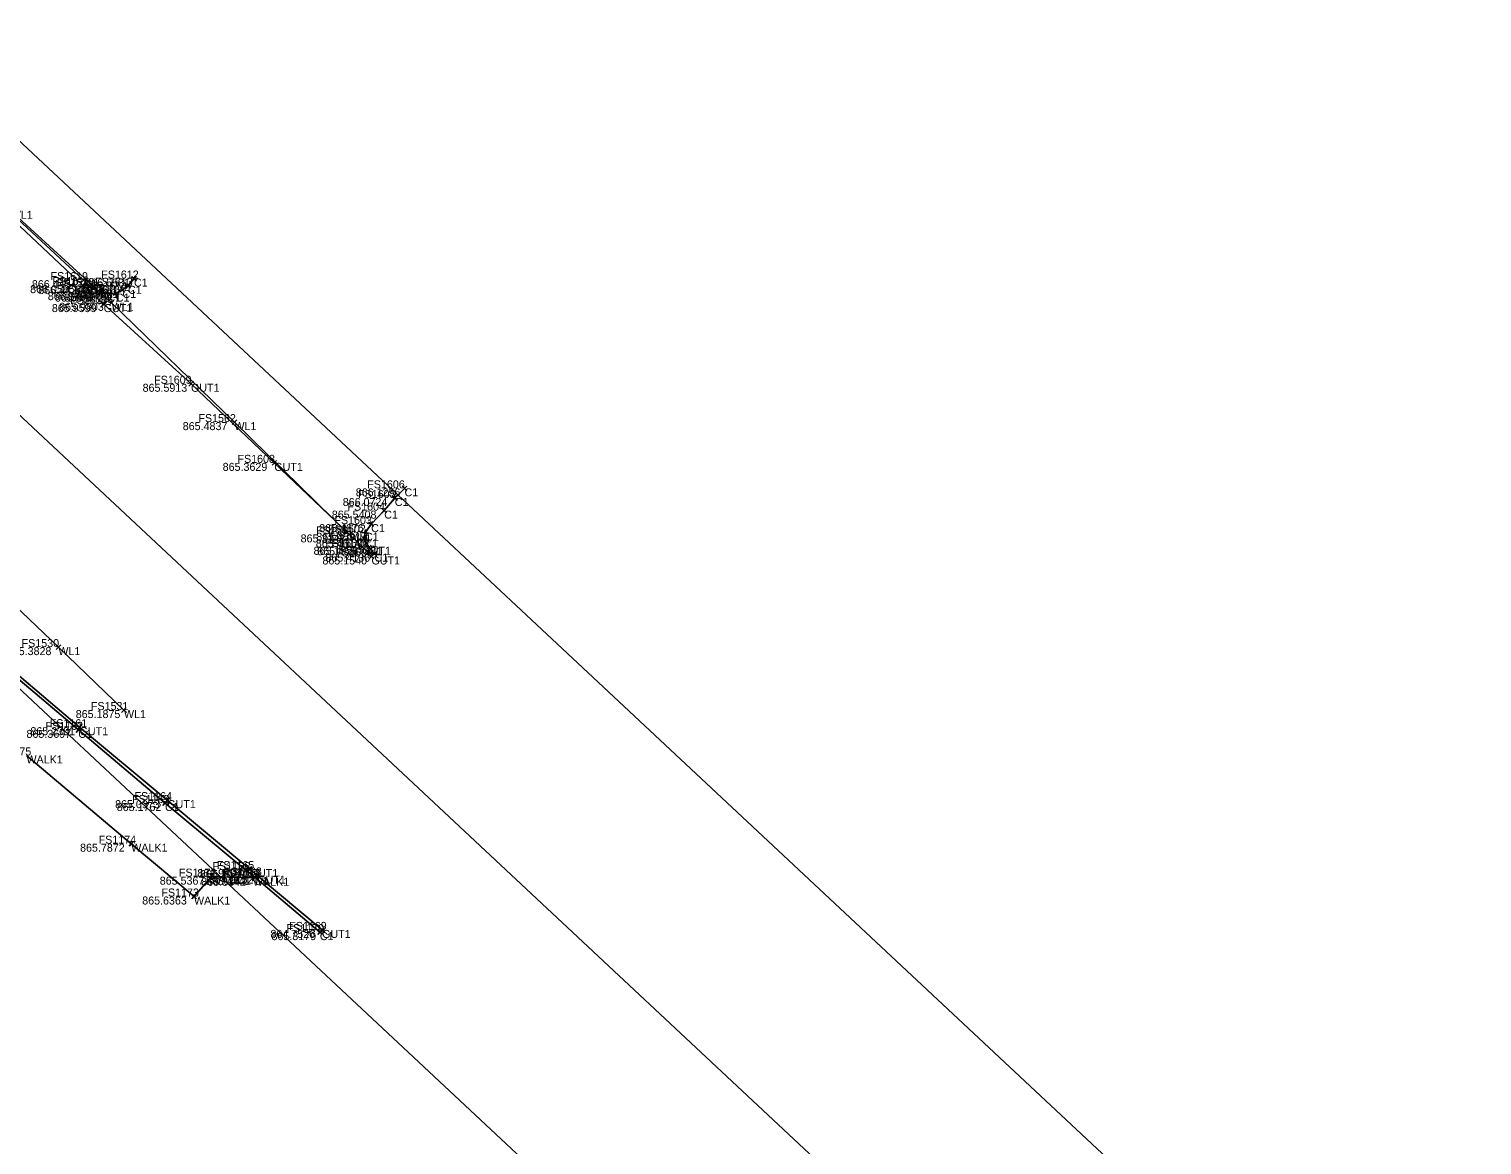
# Model space of a CAD drawing. Extents: x 1469677 to 1493262, y 375219 to 389293.
# Drawn here: x 1479767.4 to 1479985.4, y 379695.9 to 379863.2 of the extents above; entities that cross this region are included whole.
import ezdxf

# ---------------------------------------------------------------- set-up
doc = ezdxf.new("R2010")
doc.units = 0
for name, color, linetype in [('DR_X_Drive_Pipe', 7, 'Continuous'), ('DV_X_Lot_Line', 7, 'Continuous'), ('DV_X_Text', 7, 'Continuous'), ('GK_Visualization', 7, 'Continuous'), ('PNTELEV', 7, 'Continuous'), ('RD_P_Text', 7, 'Continuous'), ('RW_P_Esmt_SW', 7, 'Continuous'), ('SV_X_Mon_Cells_Found', 7, 'Continuous'), ('SV_X_Text_Elevation', 7, 'Continuous')]:
    doc.layers.add(name, color=color, linetype=linetype)

msp = doc.modelspace()

# ---------------------------------------------------------------- linework, layer by layer
at = {"layer": 'DR_X_Drive_Pipe'}
for points in [[(1479473.22, 380054.88), (1479498.74, 380029.97), (1479514.51, 380014.09), (1479533.45, 379996.74), (1479556, 379974.32), (1479574.86, 379956.27), (1479584.4, 379947.43), (1479599.6, 379932.82), (1479630.11, 379903.78), (1479644.77, 379889.72), (1479654.21, 379882.36), (1479664.27, 379872.63), (1479692.51, 379845.85), (1479712.67, 379826.69), (1479730.74, 379809.85), (1479753.15, 379788.31), (1479771.84, 379770.54), (1479781.68, 379761.1)], [(1479815.47, 379787.44), (1479798.25, 379804.28), (1479779.82, 379822.17), (1479764.7, 379835.97)]]:
    msp.add_lwpolyline(points, dxfattribs=at)
at = {"layer": 'DV_X_Lot_Line'}
msp.add_lwpolyline([(1479801.03, 379735.95), (1479794.8, 379736.12), (1479792.19, 379733.14), (1479782.77, 379741.06), (1479767.06, 379754.29)], dxfattribs=at)
at = {"layer": 'PNTELEV'}
for p, q in [((1479775.13, 379824.45), (1479775.8, 379825.19)), ((1479775.97, 379825.22), (1479775.25, 379825.91)), ((1479775.27, 379825.21), (1479775.96, 379825.93)), ((1479775.61, 379825.57), (1479775.61, 379825.57)), ((1479783.58, 379825.49), (1479782.81, 379826.12)), ((1479783.51, 379826.19), (1479782.87, 379825.42)), ((1479783.19, 379825.81), (1479783.19, 379825.81)), ((1479775.84, 379824.49), (1479775.09, 379825.15)), ((1479775.46, 379824.82), (1479775.46, 379824.82)), ((1479776.97, 379824.42), (1479776.11, 379824.94)), ((1479776.28, 379824.26), (1479776.8, 379825.11)), ((1479776.54, 379824.68), (1479776.54, 379824.68)), ((1479778.53, 379823.68), (1479777.55, 379823.86)), ((1479777.95, 379823.28), (1479778.13, 379824.26)), ((1479778.04, 379823.77), (1479778.04, 379823.77)), ((1479779.7, 379823.56), (1479778.7, 379823.56)), ((1479779.2, 379823.06), (1479779.21, 379824.06)), ((1479779.2, 379823.56), (1479779.2, 379823.56)), ((1479780.91, 379823.79), (1479780.03, 379823.31)), ((1479780.71, 379823.12), (1479780.23, 379823.99)), ((1479780.47, 379823.55), (1479780.47, 379823.55)), ((1479781.86, 379824.4), (1479781.06, 379823.8)), ((1479781.76, 379823.7), (1479781.16, 379824.5)), ((1479781.46, 379824.1), (1479781.46, 379824.1)), ((1479782.68, 379824.4), (1479781.91, 379825.04)), ((1479782.62, 379825.11), (1479781.98, 379824.34)), ((1479782.3, 379824.72), (1479782.3, 379824.72)), ((1479779.01, 379821.65), (1479778.27, 379822.32)), ((1479778.3, 379821.61), (1479778.97, 379822.35)), ((1479778.64, 379821.98), (1479778.64, 379821.98)), ((1479780.17, 379821.82), (1479779.46, 379822.51)), ((1479779.47, 379821.81), (1479780.16, 379822.53)), ((1479779.82, 379822.17), (1479779.82, 379822.17)), ((1479792.1, 379809.69), (1479791.38, 379810.38)), ((1479791.4, 379809.67), (1479792.09, 379810.4)), ((1479791.74, 379810.03), (1479791.74, 379810.03)), ((1479798.61, 379803.93), (1479797.89, 379804.63)), ((1479797.9, 379803.93), (1479798.6, 379804.64)), ((1479798.25, 379804.28), (1479798.25, 379804.28)), ((1479804.59, 379797.82), (1479803.87, 379798.51)), ((1479803.89, 379797.81), (1479804.58, 379798.53)), ((1479804.23, 379798.17), (1479804.23, 379798.17)), ((1479823.41, 379794), (1479824.13, 379794.7)), ((1479823.42, 379794.71), (1479824.12, 379794)), ((1479821.92, 379793.22), (1479822.69, 379792.58)), ((1479821.98, 379792.52), (1479822.63, 379793.29)), ((1479822.31, 379792.9), (1479822.31, 379792.9)), ((1479823.77, 379794.35), (1479823.77, 379794.35)), ((1479820.36, 379791.35), (1479821.08, 379790.66)), ((1479820.37, 379790.65), (1479821.06, 379791.37)), ((1479820.72, 379791.01), (1479820.72, 379791.01)), ((1479817.78, 379787.19), (1479817.9, 379788.19)), ((1479818.36, 379789.27), (1479819.17, 379788.69)), ((1479818.47, 379788.58), (1479819.05, 379789.39)), ((1479818.76, 379788.98), (1479818.76, 379788.98)), ((1479815.83, 379787.09), (1479815.11, 379787.79)), ((1479815.12, 379787.09), (1479815.82, 379787.8)), ((1479815.47, 379787.44), (1479815.47, 379787.44)), ((1479817.78, 379785.22), (1479817.1, 379785.95)), ((1479817.29, 379786.46), (1479818.16, 379786.96)), ((1479817.34, 379787.75), (1479818.34, 379787.63)), ((1479817.97, 379786.28), (1479817.48, 379787.15)), ((1479817.73, 379786.71), (1479817.73, 379786.71)), ((1479817.84, 379787.69), (1479817.84, 379787.69)), ((1479817.07, 379785.24), (1479817.8, 379785.93)), ((1479817.44, 379785.58), (1479817.44, 379785.58)), ((1479818.04, 379785.18), (1479818.78, 379785.85)), ((1479818.74, 379785.14), (1479818.08, 379785.89)), ((1479818.41, 379785.52), (1479818.41, 379785.52)), ((1479818.45, 379783.78), (1479819.18, 379784.47)), ((1479819.15, 379783.76), (1479818.47, 379784.49)), ((1479818.81, 379784.13), (1479818.81, 379784.13)), ((1479818.88, 379784.23), (1479819.63, 379784.89)), ((1479819.59, 379784.18), (1479818.93, 379784.93)), ((1479819.26, 379784.56), (1479819.26, 379784.56)), ((1479771.48, 379770.89), (1479772.2, 379770.2)), ((1479772.19, 379770.9), (1479771.5, 379770.18)), ((1479771.84, 379770.54), (1479771.84, 379770.54)), ((1479781.32, 379761.45), (1479782.04, 379760.75)), ((1479782.02, 379761.46), (1479781.33, 379760.74)), ((1479781.68, 379761.1), (1479781.68, 379761.1)), ((1479774.45, 379758.45), (1479775.22, 379757.81)), ((1479775.16, 379758.51), (1479774.51, 379757.75)), ((1479774.65, 379758.85), (1479775.41, 379758.2)), ((1479775.35, 379758.91), (1479774.71, 379758.14)), ((1479774.84, 379758.13), (1479774.84, 379758.13)), ((1479775.03, 379758.53), (1479775.03, 379758.53)), ((1479787.45, 379747.48), (1479788.22, 379746.84)), ((1479788.16, 379747.54), (1479787.51, 379746.78)), ((1479787.8, 379747.91), (1479788.57, 379747.27)), ((1479787.84, 379747.16), (1479787.84, 379747.16)), ((1479788.5, 379747.97), (1479787.86, 379747.2)), ((1479788.18, 379747.59), (1479788.18, 379747.59)), ((1479783.15, 379740.74), (1479782.39, 379741.38)), ((1479782.45, 379740.68), (1479783.09, 379741.44)), ((1479782.77, 379741.06), (1479782.77, 379741.06)), ((1479795.3, 379736.11), (1479794.3, 379736.14)), ((1479794.79, 379735.62), (1479794.82, 379736.62)), ((1479794.8, 379736.12), (1479794.8, 379736.12)), ((1479799.58, 379737.43), (1479800.35, 379736.79)), ((1479800.28, 379737.49), (1479799.64, 379736.72)), ((1479799.96, 379737.11), (1479799.96, 379737.11)), ((1479800.15, 379737.57), (1479800.92, 379736.93)), ((1479800.86, 379737.63), (1479800.22, 379736.87)), ((1479801.53, 379735.94), (1479800.53, 379735.97)), ((1479800.54, 379737.25), (1479800.54, 379737.25)), ((1479800.91, 379736.36), (1479801.69, 379735.73)), ((1479801.61, 379736.44), (1479800.99, 379735.65)), ((1479801.02, 379735.45), (1479801.04, 379736.45)), ((1479801.03, 379735.95), (1479801.03, 379735.95)), ((1479801.29, 379736.61), (1479802.06, 379735.97)), ((1479801.3, 379736.05), (1479801.3, 379736.05)), ((1479802, 379736.67), (1479801.36, 379735.91)), ((1479801.68, 379736.29), (1479801.68, 379736.29)), ((1479792.57, 379732.81), (1479791.81, 379733.47)), ((1479792.52, 379733.52), (1479791.86, 379732.77)), ((1479792.19, 379733.14), (1479792.19, 379733.14)), ((1479810.68, 379728.12), (1479811.45, 379727.48)), ((1479811.39, 379728.18), (1479810.74, 379727.42)), ((1479811.03, 379728.45), (1479811.8, 379727.8)), ((1479811.07, 379727.8), (1479811.07, 379727.8)), ((1479811.73, 379728.51), (1479811.09, 379727.74)), ((1479811.41, 379728.13), (1479811.41, 379728.13))]:
    msp.add_line(p, q, dxfattribs=at)
at = {"layer": 'RD_P_Text'}
for points in [[(1479818.81, 379784.13), (1479817.44, 379785.58), (1479804.23, 379798.17), (1479791.74, 379810.03), (1479778.64, 379821.98), (1479775.46, 379824.82), (1479758.38, 379840.85)], [(1479783.19, 379825.81), (1479782.3, 379824.72), (1479781.46, 379824.1), (1479780.47, 379823.55), (1479779.2, 379823.56), (1479778.04, 379823.77), (1479776.54, 379824.68), (1479775.61, 379825.57), (1479758.65, 379841.24)], [(1479819.26, 379784.56), (1479818.41, 379785.52), (1479817.73, 379786.71), (1479817.84, 379787.69), (1479818.76, 379788.98), (1479820.72, 379791.01), (1479822.31, 379792.9), (1479823.77, 379794.35)], [(1479760.56, 379770.78), (1479775.03, 379758.53), (1479788.18, 379747.59), (1479800.54, 379737.25), (1479801.68, 379736.29), (1479811.41, 379728.13)], [(1479760.19, 379770.47), (1479774.84, 379758.13), (1479787.84, 379747.16), (1479799.96, 379737.11), (1479801.3, 379736.05), (1479811.07, 379727.8)]]:
    msp.add_lwpolyline(points, dxfattribs=at)
at = {"layer": 'SV_X_Mon_Cells_Found'}
for points in [[(1477206.54, 382340.78), (1479657.33, 379947.98), (1480466.34, 379191.88)], [(1477164.63, 382297.85), (1479615.89, 379904.59), (1480413.41, 379159.22)]]:
    msp.add_lwpolyline(points, dxfattribs=at)
at = {"layer": 'SV_X_Text_Elevation'}
msp.add_line((1479636.61, 379926.28), (1480557.83, 379065.31), dxfattribs=at)

# ---------------------------------------------------------------- texts
at = {"layer": 'DV_X_Text'}
for s, p in [('866.4454', (1479767.87, 379824.37)), ('866.5531', (1479775.89, 379824.61)), ('866.0585', (1479767.61, 379823.62)), ('866.4424', (1479768.81, 379823.48)), ('866.3493', (1479770.26, 379822.57)), ('866.0897', (1479771.33, 379822.36)), ('865.9722', (1479772.78, 379822.35)), ('865.9881', (1479774.17, 379822.9)), ('866.0670', (1479774.34, 379823.52)), ('865.9599', (1479770.87, 379820.78)), ('865.9803', (1479771.96, 379820.97)), ('865.5913', (1479784.48, 379808.83)), ('865.4837', (1479790.5, 379803.08)), ('865.3629', (1479796.49, 379796.97)), ('866.0724', (1479814.5, 379791.7)), ('866.1256', (1479816.45, 379793.15)), ('865.5408', (1479812.86, 379789.81)), ('865.4676', (1479810.96, 379787.78)), ('865.3148', (1479808.18, 379786.24)), ('865.4614', (1479810.46, 379785.51)), ('865.4591', (1479810.54, 379786.49)), ('865.1926', (1479810.12, 379784.38)), ('865.4559', (1479810.67, 379784.32)), ('865.1540', (1479811.45, 379782.93)), ('865.4136', (1479811.91, 379783.36)), ('865.3828', (1479764.11, 379769.34)), ('865.1875', (1479774.45, 379759.9)), ('865.3697', (1479767.06, 379756.93)), ('865.2301', (1479767.65, 379757.33)), ('865.0973', (1479780.35, 379746.39)), ('865.1762', (1479780.6, 379745.96)), ('865.7872', (1479775.1, 379739.86)), ('865.5367', (1479787.05, 379734.92)), ('864.9404', (1479792.68, 379736.05)), ('865.1019', (1479793.07, 379735.91)), ('865.3342', (1479793.27, 379734.75)), ('865.4441', (1479794, 379734.85)), ('864.9152', (1479794.41, 379735.09)), ('865.6363', (1479784.42, 379731.94)), ('864.7526', (1479803.65, 379726.93)), ('865.3179', (1479803.81, 379726.6))]:
    msp.add_text(s, height=1.2, dxfattribs=at).set_placement(p)
at = {"layer": 'GK_Visualization'}
for s, p in [('WL1', (1479764.7, 379834.77)), ('C1', (1479775.61, 379824.37)), ('C1', (1479783.19, 379824.61)), ('GUT1', (1479775.46, 379823.62)), ('C1', (1479776.54, 379823.48)), ('C1', (1479778.04, 379822.57)), ('C1', (1479779.2, 379822.36)), ('C1', (1479780.47, 379822.35)), ('C1', (1479781.46, 379822.9)), ('C1', (1479782.3, 379823.52)), ('GUT1', (1479778.64, 379820.78)), ('WL1', (1479779.82, 379820.97)), ('GUT1', (1479791.74, 379808.83)), ('WL1', (1479798.25, 379803.08)), ('GUT1', (1479804.23, 379796.97)), ('C1', (1479822.31, 379791.7)), ('C1', (1479823.77, 379793.15)), ('C1', (1479820.72, 379789.81)), ('C1', (1479818.76, 379787.78)), ('WL1', (1479815.47, 379786.24)), ('C1', (1479817.73, 379785.51)), ('C1', (1479817.84, 379786.49)), ('GUT1', (1479817.44, 379784.38)), ('C1', (1479818.41, 379784.32)), ('GUT1', (1479818.81, 379782.93)), ('C1', (1479819.26, 379783.36)), ('WL1', (1479771.84, 379769.34)), ('WL1', (1479781.68, 379759.9)), ('C1', (1479774.84, 379756.93)), ('GUT1', (1479775.03, 379757.33)), ('WALK1', (1479767.06, 379753.09)), ('C1', (1479787.84, 379745.96)), ('GUT1', (1479788.18, 379746.39)), ('WALK1', (1479782.77, 379739.86)), ('WALK1', (1479794.8, 379734.92)), ('C1', (1479799.96, 379735.91)), ('GUT1', (1479800.54, 379736.05)), ('WALK1', (1479801.03, 379734.75)), ('C1', (1479801.3, 379734.85)), ('GUT1', (1479801.68, 379735.09)), ('WALK1', (1479792.19, 379731.94)), ('C1', (1479811.07, 379726.6)), ('GUT1', (1479811.41, 379726.93))]:
    msp.add_text(s, height=1.2, dxfattribs=at).set_placement(p)
at = {"layer": 'RW_P_Esmt_SW'}
for s, p in [('FS1619', (1479770.67, 379825.57)), ('FS1611', (1479770.98, 379824.82)), ('FS1618', (1479771.6, 379824.68)), ('FS1614', (1479776.54, 379824.1)), ('FS1613', (1479777.37, 379824.72)), ('FS1612', (1479778.27, 379825.81)), ('FS1617', (1479773.11, 379823.77)), ('FS1610', (1479773.6, 379821.98)), ('FS1616', (1479774.2, 379823.56)), ('FS1563', (1479774.41, 379822.17)), ('FS1615', (1479775.54, 379823.55)), ('FS1609', (1479786.21, 379810.03)), ('FS1562', (1479792.85, 379804.28)), ('FS1608', (1479798.71, 379798.17)), ('FS1606', (1479818.18, 379794.35)), ('FS1605', (1479816.79, 379792.9)), ('FS1604', (1479815.21, 379791.01)), ('FS1561', (1479810.52, 379787.44)), ('FS1602', (1479812.33, 379787.69)), ('FS1603', (1479813.25, 379788.98)), ('FS1607', (1479811.92, 379785.58)), ('FS1601', (1479812.66, 379786.71)), ('FS1600', (1479812.79, 379785.52)), ('FS1598', (1479813.4, 379784.13)), ('FS1599', (1479813.85, 379784.56)), ('FS1530', (1479766.33, 379770.54)), ('FS1531', (1479776.73, 379761.1)), ('FS1162', (1479769.92, 379758.13)), ('FS1161', (1479770.55, 379758.53)), ('FS1175', (1479762.16, 379754.29)), ('FS1163', (1479782.9, 379747.16)), ('FS1164', (1479783.26, 379747.59)), ('FS1174', (1479777.89, 379741.06)), ('FS1166', (1479794.96, 379737.11)), ('FS1165', (1479795.61, 379737.25)), ('FS1172', (1479789.92, 379736.12)), ('FS1167', (1479796.37, 379736.05)), ('FS1171', (1479796.59, 379735.95)), ('FS1168', (1479796.74, 379736.29)), ('FS1173', (1479787.3, 379733.14)), ('FS1169', (1479806.47, 379728.13)), ('FS1170', (1479806.07, 379727.8))]:
    msp.add_text(s, height=1.2, dxfattribs=at).set_placement(p)

doc.saveas('drawing.dxf')
